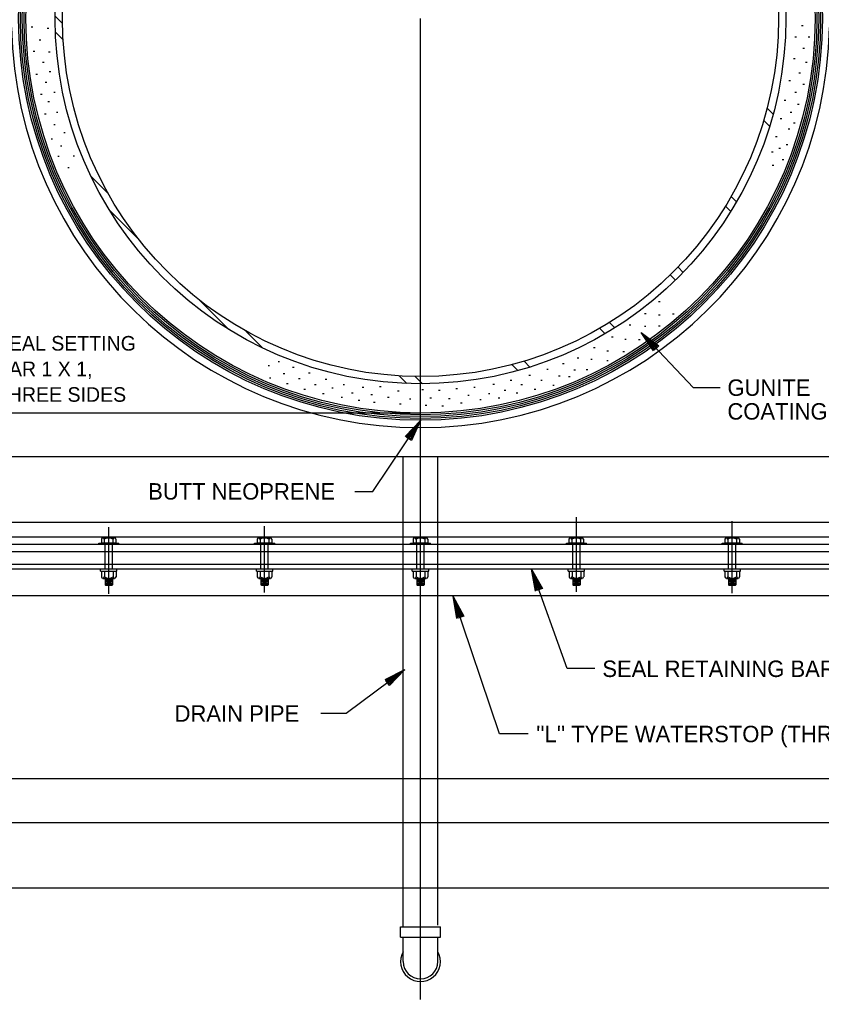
# Model space of a CAD drawing. Extents: x 22388.1 to 22405.7, y 22369.6 to 22390.4.
# Drawn here: x 22390.355 to 22392.641, y 22375.205 to 22377.998 of the extents above; entities that cross this region are included whole.
import ezdxf

# ---------------------------------------------------------------- set-up
doc = ezdxf.new("R2010")
doc.units = 0
for name, color, linetype in [('Level 1', 7, 'Continuous'), ('Level 10', 7, 'Continuous'), ('Level 2', 7, 'Continuous'), ('Level 38', 7, 'Continuous'), ('Level 4', 7, 'Continuous'), ('Level 44', 7, 'Continuous'), ('Level 50', 7, 'Continuous'), ('Level 7', 7, 'Continuous')]:
    doc.layers.add(name, color=color, linetype=linetype)

msp = doc.modelspace()

# ---------------------------------------------------------------- linework, layer by layer
at = {"layer": 'Level 1'}
for p, q in [((22390.4769, 22377.9868), (22390.4559, 22378.0077)), ((22391.4976, 22376.7516), (22391.4976, 22378.0016)), ((22390.4786, 22377.9409), (22390.4566, 22377.9628)), ((22392.5028, 22377.7286), (22392.4858, 22377.7456)), ((22392.4929, 22377.6943), (22392.4762, 22377.711)), ((22390.6064, 22377.5036), (22390.5578, 22377.5523)), ((22392.3987, 22377.4791), (22392.3835, 22377.4943)), ((22390.6945, 22377.3714), (22390.6108, 22377.4551)), ((22392.3822, 22377.4515), (22392.367, 22377.4666)), ((22392.2466, 22377.2777), (22392.2319, 22377.2924)), ((22392.2246, 22377.2555), (22392.2098, 22377.2703)), ((22390.9511, 22377.1148), (22390.8674, 22377.1985)), ((22392.0239, 22377.1027), (22392.0087, 22377.1179)), ((22392.0514, 22377.1193), (22392.0363, 22377.1345)), ((22391.0483, 22377.0618), (22390.9996, 22377.1104)), ((22391.7754, 22376.9976), (22391.7584, 22377.0146)), ((22391.8095, 22377.0077), (22391.7928, 22377.0244)), ((22391.4588, 22376.9606), (22391.4369, 22376.9826)), ((22391.5037, 22376.9599), (22391.4828, 22376.9809)), ((22391.4976, 22376.8766), (22389.1265, 22376.8766)), ((22391.4976, 22375.2046), (22391.4976, 22376.7516)), ((22391.942, 22376.3672), (22391.942, 22376.5801)), ((22392.3865, 22376.3633), (22392.3865, 22376.5678)), ((22390.6087, 22376.3614), (22390.6087, 22376.5512)), ((22391.0531, 22376.3653), (22391.0531, 22376.5535)), ((22390.5801, 22376.5055), (22390.6373, 22376.5055)), ((22390.5801, 22376.5016), (22390.5801, 22376.5055)), ((22390.5876, 22376.5172), (22390.5876, 22376.5055)), ((22390.6292, 22376.5055), (22390.5876, 22376.5055)), ((22390.625, 22376.5201), (22390.5917, 22376.5201)), ((22390.596, 22376.5173), (22390.596, 22376.5055)), ((22390.5983, 22376.4313), (22390.5983, 22376.5016)), ((22390.6191, 22376.4313), (22390.6191, 22376.5016)), ((22390.6206, 22376.5174), (22390.6206, 22376.5055)), ((22390.6292, 22376.5172), (22390.6292, 22376.5055)), ((22390.6373, 22376.5016), (22390.6373, 22376.5055)), ((22391.0245, 22376.5055), (22391.0818, 22376.5055)), ((22391.0245, 22376.5016), (22391.0245, 22376.5055)), ((22391.032, 22376.5172), (22391.032, 22376.5055)), ((22391.0737, 22376.5055), (22391.032, 22376.5055)), ((22391.0694, 22376.5201), (22391.0362, 22376.5201)), ((22391.0404, 22376.5173), (22391.0404, 22376.5055)), ((22391.0427, 22376.4313), (22391.0427, 22376.5016)), ((22391.0636, 22376.4313), (22391.0636, 22376.5016)), ((22391.0651, 22376.5174), (22391.0651, 22376.5055)), ((22391.0737, 22376.5172), (22391.0737, 22376.5055)), ((22391.0818, 22376.5016), (22391.0818, 22376.5055)), ((22391.4689, 22376.5055), (22391.5262, 22376.5055)), ((22391.4689, 22376.5016), (22391.4689, 22376.5055)), ((22391.4764, 22376.5172), (22391.4764, 22376.5055)), ((22391.5181, 22376.5055), (22391.4764, 22376.5055)), ((22391.5139, 22376.5201), (22391.4806, 22376.5201)), ((22391.4849, 22376.5173), (22391.4849, 22376.5055)), ((22391.4872, 22376.4313), (22391.4872, 22376.5016)), ((22391.508, 22376.4313), (22391.508, 22376.5016)), ((22391.5095, 22376.5174), (22391.5095, 22376.5055)), ((22391.5181, 22376.5172), (22391.5181, 22376.5055)), ((22391.5262, 22376.5016), (22391.5262, 22376.5055)), ((22391.9134, 22376.5055), (22391.9707, 22376.5055)), ((22391.9134, 22376.5016), (22391.9134, 22376.5055)), ((22391.9209, 22376.5172), (22391.9209, 22376.5055)), ((22391.9626, 22376.5055), (22391.9209, 22376.5055)), ((22391.9583, 22376.5201), (22391.9251, 22376.5201)), ((22391.9293, 22376.5173), (22391.9293, 22376.5055)), ((22391.9316, 22376.4313), (22391.9316, 22376.5016)), ((22391.9524, 22376.4313), (22391.9524, 22376.5016)), ((22391.9539, 22376.5174), (22391.9539, 22376.5055)), ((22391.9626, 22376.5172), (22391.9626, 22376.5055)), ((22391.9707, 22376.5016), (22391.9707, 22376.5055)), ((22392.3578, 22376.5055), (22392.4151, 22376.5055)), ((22392.3578, 22376.5016), (22392.3578, 22376.5055)), ((22392.3653, 22376.5172), (22392.3653, 22376.5055)), ((22392.407, 22376.5055), (22392.3653, 22376.5055)), ((22392.4028, 22376.5201), (22392.3695, 22376.5201)), ((22392.3738, 22376.5173), (22392.3738, 22376.5055)), ((22392.3761, 22376.4313), (22392.3761, 22376.5016)), ((22392.3969, 22376.4313), (22392.3969, 22376.5016)), ((22392.3984, 22376.5174), (22392.3984, 22376.5055)), ((22392.407, 22376.5172), (22392.407, 22376.5055)), ((22392.4151, 22376.5016), (22392.4151, 22376.5055)), ((22390.5853, 22376.4261), (22390.5853, 22376.4313)), ((22390.5853, 22376.4261), (22390.6321, 22376.4261)), ((22390.5879, 22376.4261), (22390.5879, 22376.4094)), ((22390.5965, 22376.4261), (22390.5965, 22376.4094)), ((22390.6211, 22376.4261), (22390.6211, 22376.4094)), ((22390.6295, 22376.4261), (22390.6295, 22376.4094)), ((22390.6321, 22376.4261), (22390.6321, 22376.4313)), ((22391.0297, 22376.4261), (22391.0297, 22376.4313)), ((22391.0297, 22376.4261), (22391.0766, 22376.4261)), ((22391.0323, 22376.4261), (22391.0323, 22376.4094)), ((22391.0409, 22376.4261), (22391.0409, 22376.4094)), ((22391.0656, 22376.4261), (22391.0656, 22376.4094)), ((22391.074, 22376.4261), (22391.074, 22376.4094)), ((22391.0766, 22376.4261), (22391.0766, 22376.4313)), ((22391.4742, 22376.4261), (22391.4742, 22376.4313)), ((22391.4742, 22376.4261), (22391.521, 22376.4261)), ((22391.4768, 22376.4261), (22391.4768, 22376.4094)), ((22391.4854, 22376.4261), (22391.4854, 22376.4094)), ((22391.51, 22376.4261), (22391.51, 22376.4094)), ((22391.5184, 22376.4261), (22391.5184, 22376.4094)), ((22391.521, 22376.4261), (22391.521, 22376.4313)), ((22391.9186, 22376.4261), (22391.9186, 22376.4313)), ((22391.9186, 22376.4261), (22391.9655, 22376.4261)), ((22391.9212, 22376.4261), (22391.9212, 22376.4094)), ((22391.9298, 22376.4261), (22391.9298, 22376.4094)), ((22391.9544, 22376.4261), (22391.9544, 22376.4094)), ((22391.9629, 22376.4261), (22391.9629, 22376.4094)), ((22391.9655, 22376.4261), (22391.9655, 22376.4313)), ((22392.363, 22376.4261), (22392.363, 22376.4313)), ((22392.363, 22376.4261), (22392.4099, 22376.4261)), ((22392.3656, 22376.4261), (22392.3656, 22376.4094)), ((22392.3743, 22376.4261), (22392.3743, 22376.4094)), ((22392.3989, 22376.4261), (22392.3989, 22376.4094)), ((22392.4073, 22376.4261), (22392.4073, 22376.4094)), ((22392.4099, 22376.4261), (22392.4099, 22376.4313)), ((22390.5921, 22376.4052), (22390.6253, 22376.4052)), ((22390.5983, 22376.4052), (22390.5983, 22376.3865)), ((22390.5983, 22376.4031), (22390.6191, 22376.4031)), ((22390.5983, 22376.3989), (22390.6191, 22376.3989)), ((22390.5983, 22376.3948), (22390.6191, 22376.3948)), ((22390.5983, 22376.3906), (22390.6191, 22376.3906)), ((22390.6035, 22376.401), (22390.6144, 22376.401)), ((22390.6035, 22376.3969), (22390.6144, 22376.3969)), ((22390.6035, 22376.3927), (22390.6144, 22376.3927)), ((22390.6191, 22376.4052), (22390.6191, 22376.3866)), ((22391.0366, 22376.4052), (22391.0698, 22376.4052)), ((22391.0427, 22376.4052), (22391.0427, 22376.3865)), ((22391.0427, 22376.4031), (22391.0636, 22376.4031)), ((22391.0427, 22376.3989), (22391.0636, 22376.3989)), ((22391.0427, 22376.3948), (22391.0636, 22376.3948)), ((22391.0427, 22376.3906), (22391.0636, 22376.3906)), ((22391.048, 22376.401), (22391.0589, 22376.401)), ((22391.048, 22376.3969), (22391.0589, 22376.3969)), ((22391.048, 22376.3927), (22391.0589, 22376.3927)), ((22391.0636, 22376.4052), (22391.0636, 22376.3866)), ((22391.481, 22376.4052), (22391.5142, 22376.4052)), ((22391.4872, 22376.4052), (22391.4872, 22376.3865)), ((22391.4872, 22376.4031), (22391.508, 22376.4031)), ((22391.4872, 22376.3989), (22391.508, 22376.3989)), ((22391.4872, 22376.3948), (22391.508, 22376.3948)), ((22391.4872, 22376.3906), (22391.508, 22376.3906)), ((22391.4924, 22376.401), (22391.5033, 22376.401)), ((22391.4924, 22376.3969), (22391.5033, 22376.3969)), ((22391.4924, 22376.3927), (22391.5033, 22376.3927)), ((22391.508, 22376.4052), (22391.508, 22376.3866)), ((22391.9254, 22376.4052), (22391.9587, 22376.4052)), ((22391.9316, 22376.4052), (22391.9316, 22376.3865)), ((22391.9316, 22376.4031), (22391.9524, 22376.4031)), ((22391.9316, 22376.3989), (22391.9524, 22376.3989)), ((22391.9316, 22376.3948), (22391.9524, 22376.3948)), ((22391.9316, 22376.3906), (22391.9524, 22376.3906)), ((22391.9368, 22376.401), (22391.9478, 22376.401)), ((22391.9368, 22376.3969), (22391.9478, 22376.3969)), ((22391.9368, 22376.3927), (22391.9478, 22376.3927)), ((22391.9524, 22376.4052), (22391.9524, 22376.3866)), ((22392.3699, 22376.4052), (22392.4031, 22376.4052)), ((22392.3761, 22376.4052), (22392.3761, 22376.3865)), ((22392.3761, 22376.4031), (22392.3969, 22376.4031)), ((22392.3761, 22376.3989), (22392.3969, 22376.3989)), ((22392.3761, 22376.3948), (22392.3969, 22376.3948)), ((22392.3761, 22376.3906), (22392.3969, 22376.3906)), ((22392.3813, 22376.401), (22392.3922, 22376.401)), ((22392.3813, 22376.3969), (22392.3922, 22376.3969)), ((22392.3813, 22376.3927), (22392.3922, 22376.3927)), ((22392.3969, 22376.4052), (22392.3969, 22376.3866)), ((22390.5983, 22376.3865), (22390.5994, 22376.3854)), ((22390.5983, 22376.3864), (22390.6191, 22376.3864)), ((22390.5994, 22376.3854), (22390.6181, 22376.3854)), ((22390.6035, 22376.3885), (22390.6144, 22376.3885)), ((22390.6191, 22376.3866), (22390.6181, 22376.3854)), ((22391.0427, 22376.3865), (22391.0438, 22376.3854)), ((22391.0427, 22376.3864), (22391.0636, 22376.3864)), ((22391.0438, 22376.3854), (22391.0625, 22376.3854)), ((22391.048, 22376.3885), (22391.0589, 22376.3885)), ((22391.0636, 22376.3866), (22391.0625, 22376.3854)), ((22391.4872, 22376.3865), (22391.4883, 22376.3854)), ((22391.4872, 22376.3864), (22391.508, 22376.3864)), ((22391.4883, 22376.3854), (22391.507, 22376.3854)), ((22391.4924, 22376.3885), (22391.5033, 22376.3885)), ((22391.508, 22376.3866), (22391.507, 22376.3854)), ((22391.9316, 22376.3865), (22391.9327, 22376.3854)), ((22391.9316, 22376.3864), (22391.9524, 22376.3864)), ((22391.9327, 22376.3854), (22391.9514, 22376.3854)), ((22391.9368, 22376.3885), (22391.9478, 22376.3885)), ((22391.9524, 22376.3866), (22391.9514, 22376.3854)), ((22392.3761, 22376.3865), (22392.3772, 22376.3854)), ((22392.3761, 22376.3864), (22392.3969, 22376.3864)), ((22392.3772, 22376.3854), (22392.3958, 22376.3854)), ((22392.3813, 22376.3885), (22392.3922, 22376.3885)), ((22392.3969, 22376.3866), (22392.3958, 22376.3854))]:
    msp.add_line(p, q, dxfattribs=at)
for radius in [1.1406, 1.1354, 1.1302]:
    msp.add_circle((22391.4976, 22378.0016), radius, dxfattribs=at)
for centre, radius, start, end in [((22390.5918, 22376.5155), 0.00456, 22.375, 157.1995), ((22390.6084, 22376.4916), 0.0285, 64.5519, 115.884), ((22390.6249, 22376.5154), 0.00469, 23.1675, 155.9991), ((22391.0362, 22376.5155), 0.00456, 22.375, 157.1995), ((22391.0528, 22376.4916), 0.0285, 64.5519, 115.884), ((22391.0694, 22376.5154), 0.00469, 23.1675, 155.9991), ((22391.4806, 22376.5155), 0.00456, 22.375, 157.1995), ((22391.4973, 22376.4916), 0.0285, 64.5519, 115.884), ((22391.5138, 22376.5154), 0.00469, 23.1675, 155.9991), ((22391.9251, 22376.5155), 0.00456, 22.375, 157.1995), ((22391.9417, 22376.4916), 0.0285, 64.5519, 115.884), ((22391.9582, 22376.5154), 0.00469, 23.1675, 155.9991), ((22392.3695, 22376.5155), 0.00456, 22.375, 157.1995), ((22392.3862, 22376.4916), 0.0285, 64.5519, 115.884), ((22392.4027, 22376.5154), 0.00469, 23.1675, 155.9991), ((22390.5921, 22376.4095), 0.00422, 180.5659, 359.4341), ((22390.6088, 22376.4255), 0.0203, 232.4343, 307.5657), ((22390.6253, 22376.4095), 0.00421, 180.4975, 359.5025), ((22391.0365, 22376.4095), 0.00422, 180.5659, 359.4341), ((22391.0532, 22376.4255), 0.0203, 232.4343, 307.5657), ((22391.0698, 22376.4095), 0.00421, 180.4975, 359.5025), ((22391.481, 22376.4095), 0.00422, 180.5659, 359.4341), ((22391.4977, 22376.4255), 0.0203, 232.4343, 307.5657), ((22391.5142, 22376.4095), 0.00421, 180.4975, 359.5025), ((22391.9254, 22376.4095), 0.00422, 180.5659, 359.4341), ((22391.9421, 22376.4255), 0.0203, 232.4343, 307.5657), ((22391.9586, 22376.4095), 0.00421, 180.4975, 359.5025), ((22392.3699, 22376.4095), 0.00422, 180.5659, 359.4341), ((22392.3866, 22376.4255), 0.0203, 232.4343, 307.5657), ((22392.4031, 22376.4095), 0.00421, 180.4975, 359.5025)]:
    msp.add_arc(centre, radius, start, end, dxfattribs=at)
at = {"layer": 'Level 10'}
msp.add_line((22391.4976, 22376.8557), (22391.4976, 22376.8766), dxfattribs=at)
at = {"layer": 'Level 2'}
for p, q in [((22392.1266, 22377.106), (22392.1266, 22377.106)), ((22392.1385, 22377.0934), (22392.1385, 22377.0934)), ((22392.7476, 22376.7516), (22390.2476, 22376.7516)), ((22392.8934, 22376.5641), (22390.1018, 22376.5641)), ((22392.9559, 22376.5016), (22390.0393, 22376.5016)), ((22392.9351, 22376.5224), (22390.0601, 22376.5224)), ((22392.9768, 22376.4807), (22390.0184, 22376.4807)), ((22393.0262, 22376.4313), (22389.9689, 22376.4313)), ((22393.0132, 22376.4443), (22389.982, 22376.4443)), ((22391.8143, 22376.4313), (22391.8143, 22376.4313)), ((22391.8202, 22376.415), (22391.8202, 22376.415)), ((22393.1018, 22376.3557), (22389.8934, 22376.3557)), ((22391.5909, 22376.3531), (22391.5909, 22376.3531)), ((22391.5965, 22376.3366), (22391.5965, 22376.3366)), ((22391.4527, 22376.1457), (22391.4527, 22376.1457)), ((22391.4388, 22376.1353), (22391.4388, 22376.1353)), ((22393.4976, 22375.8334), (22389.4976, 22375.8334))]:
    msp.add_line(p, q, dxfattribs=at)
for points in [[(22392.3517, 22376.9483), (22392.2757, 22376.9483), (22392.1266, 22377.106)], [(22392.1619, 22377.0536), (22392.1266, 22377.106), (22392.1769, 22377.0678), (22392.1641, 22377.0557), (22392.1385, 22377.0934), (22392.1727, 22377.0674), (22392.1644, 22377.0597), (22392.15, 22377.0813), (22392.1684, 22377.0671), (22392.165, 22377.0639), (22392.1619, 22377.0687)], [(22391.3101, 22376.6527), (22391.3615, 22376.6527), (22391.4976, 22376.8557)], [(22391.9942, 22376.1477), (22391.916, 22376.1477), (22391.8143, 22376.4313)], [(22391.8256, 22376.3691), (22391.8143, 22376.4313), (22391.8451, 22376.3761), (22391.8285, 22376.3701), (22391.8202, 22376.415), (22391.8411, 22376.3775), (22391.8304, 22376.3736), (22391.8258, 22376.3993), (22391.837, 22376.3788), (22391.8326, 22376.3773), (22391.8317, 22376.3829)], [(22391.8047, 22375.9618), (22391.723, 22375.9618), (22391.5909, 22376.3531)], [(22391.6011, 22376.2907), (22391.5909, 22376.3531), (22391.6207, 22376.2973), (22391.6039, 22376.2917), (22391.5965, 22376.3366), (22391.6166, 22376.2988), (22391.6059, 22376.2951), (22391.6018, 22376.3208), (22391.6126, 22376.3002), (22391.6082, 22376.2987), (22391.6073, 22376.3044)], [(22391.2133, 22376.021), (22391.2855, 22376.021), (22391.4527, 22376.1457)], [(22391.3966, 22376.1167), (22391.4527, 22376.1457), (22391.4089, 22376.1001), (22391.3984, 22376.1143), (22391.4388, 22376.1353), (22391.4091, 22376.1044), (22391.4023, 22376.1135), (22391.4255, 22376.1253), (22391.4092, 22376.1087), (22391.4064, 22376.1124), (22391.4116, 22376.115)]]:
    msp.add_lwpolyline(points, dxfattribs=at)
for radius in [1.1458, 1.125, 1.0417, 1.0208]:
    msp.add_circle((22391.4976, 22378.0016), radius, dxfattribs=at)
msp.add_arc((22391.4976, 22378.0016), 1.1667, 181.279, 358.721, dxfattribs=at)
at = {"layer": 'Level 38'}
for p, q in [((22391.4481, 22375.4119), (22391.4481, 22376.7516)), ((22391.5471, 22375.4166), (22391.5471, 22376.7516)), ((22391.4406, 22375.4119), (22391.5545, 22375.4119)), ((22391.4406, 22375.3822), (22391.4406, 22375.4119)), ((22391.5545, 22375.3822), (22391.5545, 22375.4119)), ((22391.4406, 22375.3822), (22391.5545, 22375.3822)), ((22391.4481, 22375.3125), (22391.4481, 22375.3822)), ((22391.5471, 22375.3125), (22391.5471, 22375.3822))]:
    msp.add_line(p, q, dxfattribs=at)
at = {"layer": 'Level 44'}
for p, q in [((22390.3876, 22377.9776), (22390.3921, 22377.9776)), ((22390.433, 22377.974), (22390.4375, 22377.974)), ((22392.5839, 22377.9811), (22392.5884, 22377.9811)), ((22390.4103, 22377.9403), (22390.4148, 22377.9403)), ((22392.5649, 22377.9492), (22392.5694, 22377.9492)), ((22392.6028, 22377.9492), (22392.6073, 22377.9492)), ((22390.3933, 22377.9084), (22390.3978, 22377.9084)), ((22390.4368, 22377.9066), (22390.4413, 22377.9066)), ((22392.5877, 22377.9173), (22392.5922, 22377.9173)), ((22390.4197, 22377.8765), (22390.4242, 22377.8765)), ((22392.5612, 22377.8871), (22392.5657, 22377.8871)), ((22392.5952, 22377.8765), (22392.5997, 22377.8765)), ((22390.4008, 22377.8428), (22390.4053, 22377.8428)), ((22390.4387, 22377.8499), (22390.4432, 22377.8499)), ((22392.5763, 22377.8463), (22392.5808, 22377.8463)), ((22390.4273, 22377.8197), (22390.4318, 22377.8197)), ((22392.5479, 22377.825), (22392.5524, 22377.825)), ((22392.5877, 22377.8144), (22392.5922, 22377.8144)), ((22390.4519, 22377.7913), (22390.4564, 22377.7913)), ((22392.5649, 22377.7913), (22392.5694, 22377.7913)), ((22390.4141, 22377.786), (22390.4186, 22377.786)), ((22390.4349, 22377.7647), (22390.4394, 22377.7647)), ((22392.5347, 22377.7682), (22392.5392, 22377.7682)), ((22390.4595, 22377.7345), (22390.464, 22377.7345)), ((22392.5517, 22377.7345), (22392.5562, 22377.7345)), ((22392.5725, 22377.7576), (22392.577, 22377.7576)), ((22390.4254, 22377.7292), (22390.4299, 22377.7292)), ((22392.5233, 22377.7168), (22392.5278, 22377.7168)), ((22392.5612, 22377.7044), (22392.5657, 22377.7044)), ((22390.4519, 22377.699), (22390.4564, 22377.699)), ((22390.4803, 22377.676), (22390.4848, 22377.676)), ((22392.546, 22377.6866), (22392.5505, 22377.6866)), ((22390.4443, 22377.6582), (22390.4488, 22377.6582)), ((22392.5101, 22377.6653), (22392.5146, 22377.6653)), ((22390.4708, 22377.6387), (22390.4753, 22377.6387)), ((22392.4987, 22377.621), (22392.5032, 22377.621)), ((22392.5195, 22377.6316), (22392.524, 22377.6316)), ((22392.5404, 22377.6423), (22392.5449, 22377.6423)), ((22390.4632, 22377.6086), (22390.4677, 22377.6086)), ((22390.5068, 22377.6103), (22390.5113, 22377.6103)), ((22392.529, 22377.5997), (22392.5335, 22377.5997)), ((22390.4916, 22377.5766), (22390.4961, 22377.5766)), ((22392.5006, 22377.5837), (22392.5051, 22377.5837)), ((22392.176, 22377.1944), (22392.1805, 22377.1944)), ((22392.1367, 22377.1602), (22392.1412, 22377.1602)), ((22392.176, 22377.1562), (22392.1805, 22377.1562)), ((22392.2161, 22377.1595), (22392.2206, 22377.1595)), ((22392.0924, 22377.1279), (22392.0969, 22377.1279)), ((22392.136, 22377.1239), (22392.1405, 22377.1239)), ((22392.176, 22377.1252), (22392.1805, 22377.1252)), ((22392.0425, 22377.0936), (22392.047, 22377.0936)), ((22391.9912, 22377.0633), (22391.9957, 22377.0633)), ((22392.0798, 22377.087), (22392.0843, 22377.087)), ((22392.1191, 22377.0864), (22392.1236, 22377.0864)), ((22391.9441, 22377.0343), (22391.9486, 22377.0343)), ((22392.0292, 22377.0541), (22392.0337, 22377.0541)), ((22392.0748, 22377.0521), (22392.0793, 22377.0521)), ((22391.0629, 22377.0124), (22391.0674, 22377.0124)), ((22391.0913, 22377.0231), (22391.0958, 22377.0231)), ((22391.1329, 22377.0071), (22391.1374, 22377.0071)), ((22391.9028, 22377.0178), (22391.9073, 22377.0178)), ((22391.9828, 22377.0304), (22391.9873, 22377.0304)), ((22392.0285, 22377.0264), (22392.033, 22377.0264)), ((22391.0667, 22376.977), (22391.0712, 22376.977)), ((22391.1064, 22376.9894), (22391.1109, 22376.9894)), ((22391.1783, 22376.9912), (22391.1828, 22376.9912)), ((22391.8064, 22376.9841), (22391.8109, 22376.9841)), ((22391.8574, 22377.0018), (22391.8619, 22377.0018)), ((22391.8915, 22376.9823), (22391.896, 22376.9823)), ((22391.9199, 22376.9805), (22391.9244, 22376.9805)), ((22391.935, 22377), (22391.9395, 22377)), ((22391.9701, 22377.0007), (22391.9746, 22377.0007)), ((22391.1159, 22376.961), (22391.1204, 22376.961)), ((22391.1499, 22376.9752), (22391.1544, 22376.9752)), ((22391.1953, 22376.9575), (22391.1998, 22376.9575)), ((22391.2256, 22376.9734), (22391.2301, 22376.9734)), ((22391.2445, 22376.9486), (22391.249, 22376.9486)), ((22391.2767, 22376.9575), (22391.2812, 22376.9575)), ((22391.3315, 22376.9504), (22391.336, 22376.9504)), ((22391.3807, 22376.9521), (22391.3852, 22376.9521)), ((22391.6493, 22376.9504), (22391.6538, 22376.9504)), ((22391.7042, 22376.9592), (22391.7087, 22376.9592)), ((22391.7534, 22376.9699), (22391.7579, 22376.9699)), ((22391.7837, 22376.9575), (22391.7882, 22376.9575)), ((22391.8404, 22376.9699), (22391.8449, 22376.9699)), ((22391.8745, 22376.9557), (22391.879, 22376.9557)), ((22391.1651, 22376.945), (22391.1696, 22376.945)), ((22391.218, 22376.9326), (22391.2225, 22376.9326)), ((22391.271, 22376.922), (22391.2755, 22376.922)), ((22391.3013, 22376.9344), (22391.3058, 22376.9344)), ((22391.3561, 22376.9291), (22391.3606, 22376.9291)), ((22391.4034, 22376.922), (22391.4079, 22376.922)), ((22391.4318, 22376.9397), (22391.4363, 22376.9397)), ((22391.5018, 22376.9433), (22391.5063, 22376.9433)), ((22391.5491, 22376.9415), (22391.5536, 22376.9415)), ((22391.5983, 22376.9468), (22391.6028, 22376.9468)), ((22391.6323, 22376.9273), (22391.6368, 22376.9273)), ((22391.691, 22376.9326), (22391.6955, 22376.9326)), ((22391.7364, 22376.9415), (22391.7409, 22376.9415)), ((22391.7704, 22376.9344), (22391.7749, 22376.9344)), ((22391.8215, 22376.945), (22391.826, 22376.945)), ((22391.3202, 22376.9131), (22391.3247, 22376.9131)), ((22391.3637, 22376.9078), (22391.3682, 22376.9078)), ((22391.4375, 22376.9025), (22391.442, 22376.9025)), ((22391.4659, 22376.9166), (22391.4704, 22376.9166)), ((22391.5113, 22376.8989), (22391.5158, 22376.8989)), ((22391.5245, 22376.9202), (22391.529, 22376.9202)), ((22391.5586, 22376.8971), (22391.5631, 22376.8971)), ((22391.5775, 22376.9184), (22391.582, 22376.9184)), ((22391.6115, 22376.906), (22391.616, 22376.906)), ((22391.6664, 22376.9149), (22391.6709, 22376.9149)), ((22391.7193, 22376.9202), (22391.7238, 22376.9202))]:
    msp.add_line(p, q, dxfattribs=at)
at = {"layer": 'Level 50'}
for p, q in [((22391.4879, 22376.8414), (22391.4879, 22376.8414)), ((22391.4976, 22376.8557), (22391.4976, 22376.8557)), ((22390.6295, 22376.4094), (22390.6295, 22376.4094)), ((22391.074, 22376.4094), (22391.074, 22376.4094)), ((22391.5184, 22376.4094), (22391.5184, 22376.4094)), ((22391.9629, 22376.4094), (22391.9629, 22376.4094)), ((22392.4073, 22376.4094), (22392.4073, 22376.4094))]:
    msp.add_line(p, q, dxfattribs=at)
msp.add_lwpolyline([(22391.4543, 22376.8097), (22391.4976, 22376.8557), (22391.4715, 22376.7982), (22391.4568, 22376.8081), (22391.4879, 22376.8414), (22391.4702, 22376.8023), (22391.4608, 22376.8086), (22391.4787, 22376.8275), (22391.4689, 22376.8064), (22391.465, 22376.809), (22391.469, 22376.8131)], dxfattribs=at)
for radius, start, end in [(0.0569, 150.3252, 29.6748), (0.0495, 180, 0)]:
    msp.add_arc((22391.4976, 22375.3125), radius, start, end, dxfattribs=at)
at = {"layer": 'Level 7'}
for p, q in [((22393.4976, 22375.7084), (22389.4976, 22375.7084)), ((22393.4976, 22375.5215), (22389.4976, 22375.5215))]:
    msp.add_line(p, q, dxfattribs=at)

# ---------------------------------------------------------------- texts
at = {"layer": 'Level 4'}
for s, height, p in [('SEAL SETTING', 0.041667, (22390.2868, 22377.0545)), ('BAR 1 X 1,', 0.04167, (22390.2868, 22376.9816)), ('THREE SIDES', 0.041667, (22390.2868, 22376.9086)), ('GUNITE', 0.04688, (22392.3727, 22376.9255)), ('COATING', 0.04688, (22392.3727, 22376.8578)), ('BUTT NEOPRENE', 0.046875, (22390.7211, 22376.6297)), ('SEAL RETAINING BAR (THREE SIDES)', 0.046875, (22392.0161, 22376.1239)), ('DRAIN PIPE', 0.04688, (22390.7965, 22375.9964)), ("''L'' TYPE WATERSTOP (THREE SIDES)", 0.046875, (22391.8274, 22375.9379))]:
    msp.add_text(s, height=height, dxfattribs=at).set_placement(p)

doc.saveas('drawing.dxf')
